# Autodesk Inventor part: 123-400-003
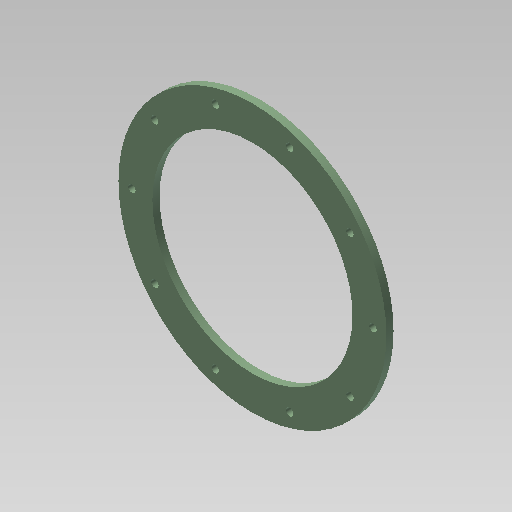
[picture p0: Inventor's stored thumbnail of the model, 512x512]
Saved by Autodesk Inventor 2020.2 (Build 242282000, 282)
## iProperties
Created: 2006-08
Part Number: 123-400-003
Material: Aluminium-6061
Document SubType Name: Modeling
Designer: F.Stasiak
Description: Kołnierz
Mass: 10407.6 g
Surface Area: 4795.48 cm^2
Volume: 3840.44 cm^3
Density: 2.71 g/cm^3
Appearance: Zielony pastelowy
Manager: www.cadconsulting.pl
Company: Fabian Stasiak CAD Consulting
KODMAT: 13-1456
Author: F.Stasiak
Subject: Zbiór ćwiczeń. Autodesk Inventor 2020. Kurs podstawowy
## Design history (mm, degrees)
sketch "Szkic1"
  geometry: C1 r 375 at (0, 0) reference; C2 r 10 at (-273.043, -198.378) reference; C3 r 10 at (-104.293, -320.982) reference; C4 r 10 at (104.293, -320.982) reference; C5 r 10 at (273.043, -198.378) reference; C6 r 10 at (337.5, 0) reference; C7 r 10 at (273.043, 198.378) reference; C8 r 10 at (104.293, 320.982) reference; C9 r 10 at (-104.293, 320.982) reference; C10 r 10 at (-273.043, 198.378) reference; C11 r 10 at (-337.5, 0) reference; C12 r 300 at (0, 0) reference; C13 r 375 at (0, 0) reference; 1 further point
  constraints: 1 coincident
extrude "Wyciągnięcie proste1" new body sketch "Szkic1" distance "d0" = 20; taper "d1" = 0 deg
sketch "Szkic2"
  geometry: C1 r 8.647 at (-337.5, 0) reference; 1 further point
  constraints: 1 coincident
hole "Otwór1" sketch "Szkic2" at (-337.5, 0) diameter "d2" = 21; stored, may be unused: countersink angle "d6" = 90 deg, drill point angle "d8" = 118 deg; dims "d3" = 6, "d4" = 4, "d5" = 2, "d7" = 8
pattern_circular "Szyk kołowy1" dims angle "d10" = 360 deg
sketch "Szkic3"
  geometry: C1 r 300 at (0, 0) reference; C2 r 280 at (0, 0)
  constraints: 1 centre point, 1 coincident
  dimensions: "d12" = 560 diameter of C2
extrude "Wyciągnięcie proste2" join sketch "Szkic3" distance "d13" = 20 (= d0); taper "d14" = 0 deg
node "Bryła1"
node "Korpusy bryłowe"
node "Korpusy powierzchniowe"
node "Odniesienie1"
node "Odniesienie2"
node "Odniesienie3"
